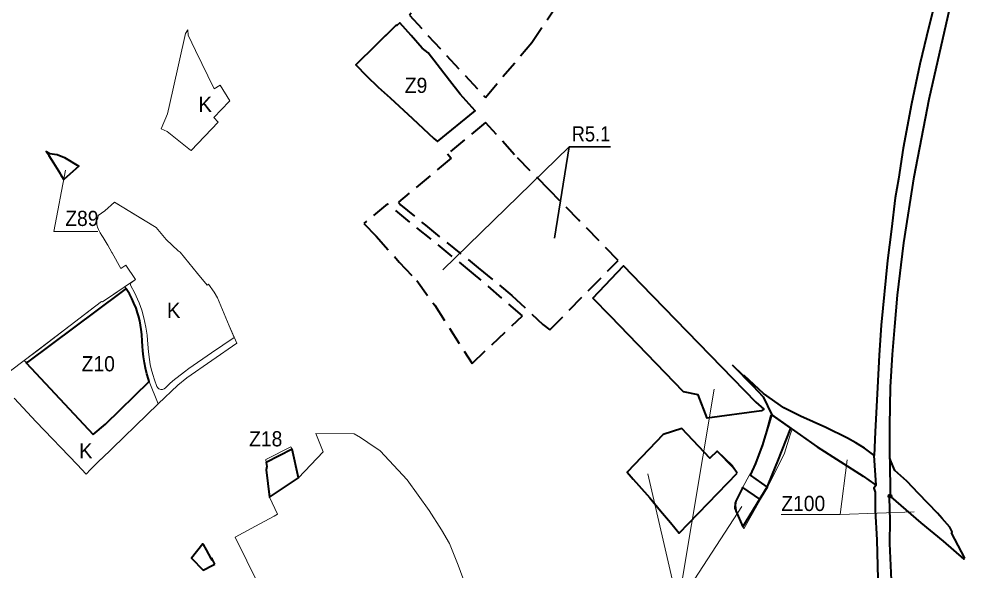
# Model space of a CAD drawing. Extents: x -650276 to -642489, y -1074311 to -1066658.
# Drawn here: x -646724 to -645222, y -1072621 to -1071749 of the extents above; entities that cross this region are included whole.
import ezdxf

# ---------------------------------------------------------------- set-up
doc = ezdxf.new("R2010")
doc.units = 0
doc.header["$LTSCALE"] = 9.6
doc.header["$PDMODE"] = 32
doc.header["$PDSIZE"] = 4.8
doc.linetypes.add('MEDIUM_DASHED', pattern=[4.5, 3, -1.5])
for name, color, linetype, lineweight in [('44', 7, 'Continuous', 40), ('45', 7, 'Continuous', 40), ('46', 7, 'Continuous', 13), ('47', 7, 'Continuous', 13), ('48', 7, 'Continuous', 13), ('61', 7, 'MEDIUM_DASHED', 40), ('62', 7, 'Continuous', 35), ('63', 7, 'Continuous', 13)]:
    doc.layers.add(name, color=color, linetype=linetype, lineweight=lineweight)

msp = doc.modelspace()

# ---------------------------------------------------------------- linework, layer by layer
at = {"layer": '44'}
for points in [[(-645347.551, -1072443.527), (-645347.677, -1072391.355), (-645346.62, -1072330.914), (-645343.458, -1072278.998), (-645339.908, -1072235.158), (-645335.367, -1072185.207), (-645325.498, -1072102.789), (-645309.01, -1071998.147), (-645285.617, -1071875.733), (-645244.798, -1071696.585), (-645235.793, -1071663.703), (-645230.436, -1071634.261), (-645227.905, -1071625.277), (-645222.48, -1071606.08)], [(-645261.094, -1071645.025), (-645264.841, -1071657.687), (-645269.077, -1071687.396), (-645274.868, -1071717.176), (-645286.175, -1071761.228), (-645300.076, -1071820.179), (-645313.153, -1071883.081)], [(-645313.153, -1071883.081), (-645326.343, -1071952.807), (-645334.118, -1072001.954), (-645339.455, -1072031.565), (-645344.819, -1072081.225), (-645351.358, -1072130.815), (-645361.317, -1072232.824), (-645364.435, -1072280.268), (-645366.951, -1072331.609), (-645370.624, -1072401.447), (-645372.228, -1072438.764)], [(-645369.364, -1072485.931), (-645372.228, -1072438.764), (-645373.099, -1072438.135), (-645387.894, -1072427.453), (-645401.441, -1072419.033), (-645414.631, -1072411.611), (-645448.831, -1072394.325), (-645488.64, -1072376.782), (-645515.437, -1072363.447), (-645547.593, -1072340.827), (-645577.33, -1072312.704), (-645579.217, -1072312.425), (-645596.405, -1072296.114)], [(-645596.405, -1072296.114), (-645564.4, -1072328.61), (-645547.72, -1072346.19), (-645534.301, -1072374.332), (-645462.646, -1072425.015)], [(-645462.646, -1072425.015), (-645389.731, -1072471.612), (-645372.013, -1072484.069), (-645369.364, -1072485.931)], [(-645339.904, -1072462.677), (-645342.953, -1072455.042), (-645347.551, -1072443.527), (-645347.292, -1072502.877)], [(-645228.96, -1072600.865), (-645249.9, -1072561.25), (-645248.967, -1072559.511), (-645252.768, -1072552.178), (-645265.009, -1072538.358), (-645272.276, -1072530.154), (-645302.303, -1072499.014), (-645320.805, -1072479.495), (-645339.904, -1072462.677)], [(-645369.364, -1072485.931), (-645372.72, -1072490.314), (-645370.928, -1072496.619), (-645370.755, -1072525.734), (-645368.173, -1072571.881), (-645366.022, -1072654.462), (-645364.524, -1072682.575), (-645364.786, -1072692.977), (-645362.708, -1072714.781)], [(-645338.023, -1072755.969), (-645339.96, -1072721.587), (-645344.152, -1072658.857), (-645347.795, -1072577.893), (-645347.214, -1072540.97), (-645348.253, -1072505.583), (-645347.292, -1072502.877)], [(-645347.292, -1072502.877), (-645346.093, -1072503.921), (-645298.498, -1072545.352)], [(-645298.498, -1072545.352), (-645263.217, -1072574.314), (-645230.845, -1072602.888), (-645228.96, -1072600.865)]]:
    msp.add_lwpolyline(points, dxfattribs=at)
msp.add_lwpolyline([(-646652.18, -1071967.73), (-646629.655, -1071981.343), (-646653.198, -1072002.544), (-646657.32, -1071995.98), (-646658.79, -1071993.62), (-646669.31, -1071976.77), (-646676.79, -1071964.97), (-646681.07, -1071958.16), (-646675.99, -1071961.64), (-646663.87, -1071963.26)], close=True, dxfattribs=at)
at = {"layer": '44', "lineweight": 13}
for points in [[(-646599.686, -1072084.891), (-646669.193, -1072084.891), (-646650.508, -1071987.658)], [(-646599.686, -1072084.891), (-646669.193, -1072084.891), (-646650.508, -1071987.658)], [(-645519.31, -1072532.095), (-645425.882, -1072532.095), (-645415.202, -1072445.813), (-645425.882, -1072532.095), (-645309.26, -1072527.964)], [(-645519.31, -1072532.095), (-645425.882, -1072532.095), (-645415.202, -1072445.813), (-645425.882, -1072532.095), (-645309.26, -1072527.964)]]:
    msp.add_lwpolyline(points, dxfattribs=at)
at = {"layer": '44'}
msp.add_point((-645347.292, -1072502.877), dxfattribs=at)
at = {"layer": '45'}
msp.add_line((-646417.787, -1072612.168), (-646414.77, -1072610.61), dxfattribs=at)
for points in [[(-646102.04, -1071906.4), (-646068.317, -1071937.555), (-646062.91, -1071942.55), (-646002.93, -1071893.984), (-646026.64, -1071867.44), (-646043.49, -1071845.87), (-646077.32, -1071802.59), (-646087, -1071795), (-646104.5, -1071774.86), (-646122.16, -1071754.78), (-646127.12, -1071759.15), (-646127.84, -1071758.53), (-646191.57, -1071821.44), (-646174.69, -1071838.69), (-646156.59, -1071856.53), (-646137.74, -1071873.31)], [(-645817.219, -1072189.975), (-645768.649, -1072139.283), (-645740.45, -1072168.23), (-645559.34, -1072354.42), (-645546.82, -1072365.72), (-645550.41, -1072368.47), (-645636.37, -1072379.57), (-645650.78, -1072342.73), (-645674, -1072338), (-645789.298, -1072218.833)], [(-646606.848, -1072405.785), (-646587.666, -1072389.082), (-646518.208, -1072321.92), (-646519.417, -1072318.408), (-646522.007, -1072309.932), (-646524.282, -1072300.849), (-646526, -1072292.201), (-646527.5, -1072282.657), (-646528.566, -1072273.308), (-646529.182, -1072265.941), (-646529.607, -1072258.124), (-646530.188, -1072247.442), (-646530.892, -1072239.747), (-646531.93, -1072232.861), (-646533.286, -1072226.031), (-646535.344, -1072217.844), (-646536.772, -1072213.218), (-646539.168, -1072206.122), (-646539.168, -1072206.122), (-646542.484, -1072197.985), (-646546.09, -1072190.428), (-646549.793, -1072183.38), (-646554.56, -1072175.629), (-646555.051, -1072174.933), (-646563.299, -1072181.091), (-646710.684, -1072291.133), (-646712.634, -1072292.59)], [(-645503.98, -1072395.64), (-645532.75, -1072375.41), (-645535.05, -1072376.72), (-645549.6, -1072423.39), (-645551.54, -1072428.66), (-645559.92, -1072451.41), (-645568.38, -1072469.68), (-645541.56, -1072488.74), (-645553.35, -1072508.1), (-645579.92, -1072489.22), (-645581.13, -1072491), (-645591.06, -1072511.06), (-645592.08, -1072517.43), (-645591.03, -1072526.14), (-645579.76, -1072551.45), (-645541.09, -1072487.98), (-645533.15, -1072468.21), (-645524.87, -1072447.61)], [(-645588.78, -1072467), (-645594.83, -1072458.48), (-645596.43, -1072455.42), (-645620.56, -1072432), (-645632.1, -1072442.93), (-645676.53, -1072396.16), (-645706.039, -1072405.769), (-645763.06, -1072465.26), (-645753.128, -1072476.383), (-645744.38, -1072486.18), (-645726.95, -1072505.7), (-645709.92, -1072526.3), (-645694.51, -1072544.93), (-645680.87, -1072561.42)], [(-645588.78, -1072467), (-645594.83, -1072458.48), (-645620.56, -1072432), (-645632.1, -1072442.93), (-645676.53, -1072396.16), (-645706.039, -1072405.769), (-645763.06, -1072465.26), (-645753.128, -1072476.383), (-645744.38, -1072486.18), (-645726.95, -1072505.7), (-645709.92, -1072526.3), (-645694.51, -1072544.93), (-645680.87, -1072561.42)], [(-646333.34, -1072461.67), (-646328.45, -1072504.81), (-646282.47, -1072474.34), (-646292.44, -1072428.89), (-646333.33, -1072450.12), (-646332.68, -1072456.19)], [(-646333.34, -1072461.67), (-646328.45, -1072504.81), (-646282.47, -1072474.34), (-646292.44, -1072428.89), (-646333.33, -1072450.12), (-646332.68, -1072456.19)]]:
    msp.add_lwpolyline(points, close=True, dxfattribs=at)
for points in [[(-646420.36, -1072601.78), (-646427.95, -1072588.07), (-646432.57, -1072579.75), (-646433.36, -1072578.45), (-646451.458, -1072601.008), (-646433.024, -1072620.04), (-646417.787, -1072612.168)], [(-646414.77, -1072610.61), (-646419.11, -1072602.03), (-646419.47, -1072601.31), (-646419.02, -1072604.18), (-646420.36, -1072601.78)]]:
    msp.add_lwpolyline(points, dxfattribs=at)
at = {"layer": '46'}
for q in [(-645625.498, -1072333.934), (-645729.938, -1072467.657), (-645729.938, -1072467.657), (-645581.338, -1072519.311)]:
    msp.add_line((-645682.434, -1072673.943), q, dxfattribs=at)
at = {"layer": '47'}
msp.add_line((-646490.111, -1071926.754), (-646453.04, -1071956.3), dxfattribs=at)
for points in [[(-646453.04, -1071956.3), (-646451.87, -1071956.88), (-646409.4, -1071912.17), (-646416.2, -1071904.81), (-646391.83, -1071879.32), (-646390.732, -1071878.171), (-646405.99, -1071853.26), (-646415.46, -1071859.05), (-646445.115, -1071798.418), (-646456.96, -1071774.2), (-646457.52, -1071765.98), (-646461.09, -1071771.76), (-646480.81, -1071861.18), (-646489.34, -1071898.61), (-646499.741, -1071922.455), (-646490.111, -1071926.754)], [(-646507.28, -1072078.4), (-646530.073, -1072064.559), (-646573.05, -1072038.46), (-646588.75, -1072052.06), (-646598.827, -1072059.244), (-646599.86, -1072063.71), (-646601, -1072067.55), (-646601.42, -1072071.01), (-646601.16, -1072074.07), (-646600.8, -1072075.94), (-646600.22, -1072077.86), (-646598.67, -1072081.55), (-646595.86, -1072086.82), (-646593.13, -1072091.01), (-646591.02, -1072094.4), (-646585.08, -1072104.81), (-646583.9, -1072106.42), (-646577.41, -1072117.76), (-646577.08, -1072118.7), (-646563.11, -1072143.03), (-646555.49, -1072138.17), (-646539.94, -1072160.83), (-646548.676, -1072166.737)], [(-646472.72, -1072115.38), (-646491.69, -1072097.45), (-646507.28, -1072078.4)], [(-646426.98, -1072169.74), (-646441.961, -1072151.281), (-646469.41, -1072117.44), (-646472.72, -1072115.38)], [(-646548.676, -1072166.737), (-646547.606, -1072170.835), (-646541.822, -1072181.102), (-646534.527, -1072197.411), (-646530.167, -1072209.31), (-646526.798, -1072221.011), (-646523.628, -1072235.883)], [(-646415.84, -1072180.43), (-646424.56, -1072167.96), (-646426.98, -1072169.74)], [(-646731.82, -1072348.2), (-646696.83, -1072385.81), (-646632.356, -1072453.247), (-646618.158, -1072468.098), (-646611.091, -1072460.994), (-646594.606, -1072444.422), (-646594.561, -1072444.38), (-646504.244, -1072357.026), (-646518.208, -1072321.92), (-646587.666, -1072389.082), (-646606.848, -1072405.785), (-646712.634, -1072292.59), (-646563.299, -1072181.091), (-646556.591, -1072176.083), (-646555.051, -1072174.933), (-646556.693, -1072172.16), (-646568.051, -1072179.84), (-646592.2, -1072196.17), (-646593.85, -1072195.48), (-646614.075, -1072210.952), (-646643.55, -1072233.5), (-646693.58, -1072271.606), (-646716.167, -1072288.809), (-646737.449, -1072305.019)], [(-646391.77, -1072233.91), (-646410.68, -1072189.36), (-646415.84, -1072180.43)], [(-646523.628, -1072235.883), (-646523.628, -1072235.883), (-646521.646, -1072248.378), (-646521.051, -1072256.707), (-646519.756, -1072274.861), (-646518.079, -1072287.051), (-646516.692, -1072294.983), (-646515.305, -1072301.925), (-646512.729, -1072311.048), (-646509.954, -1072319.377), (-646506.189, -1072329.889), (-646504.802, -1072331.971), (-646503.018, -1072333.459), (-646500.244, -1072334.45), (-646497.569, -1072334.55), (-646494.794, -1072333.558), (-646492.813, -1072332.07), (-646486.273, -1072325.526), (-646480.923, -1072320.667), (-646462.79, -1072306.784), (-646455.557, -1072301.131), (-646420.085, -1072276.737), (-646384.056, -1072252.138), (-646391.77, -1072233.91)], [(-645999.622, -1072714.927), (-646006.66, -1072681.4), (-646019.16, -1072642.35), (-646030.17, -1072612.31), (-646043.87, -1072578.12), (-646056.42, -1072556.49), (-646075.82, -1072525.54), (-646110.61, -1072477.49), (-646153.49, -1072431.54), (-646172.81, -1072418.2), (-646184.449, -1072410.256), (-646194.19, -1072404.62), (-646254.75, -1072404.25), (-646243.17, -1072432.88), (-646282.47, -1072474.34), (-646328.45, -1072504.81), (-646315.452, -1072531.573)], [(-646315.452, -1072531.573), (-646320.62, -1072534.6), (-646350.18, -1072550.59), (-646382.41, -1072568.01), (-646345.6, -1072642.55), (-646368.51, -1072652.81), (-646371.66, -1072654.2), (-646342.08, -1072717.43), (-646367.72, -1072730.68), (-646321.171, -1072780.535), (-646292.17, -1072811.6), (-646261.97, -1072849.66), (-646255.39, -1072850.83), (-646249.04, -1072847.16), (-646253.56, -1072838.8), (-646288.27, -1072810.22), (-646199.72, -1072763.1), (-646194.296, -1072760.193)]]:
    msp.add_lwpolyline(points, dxfattribs=at)
at = {"layer": '61'}
for points in [[(-645909.13, -1071478.56), (-645989, -1071611), (-646107, -1071743), (-645987.026, -1071872.902), (-645913.616, -1071786.041), (-645835.644, -1071670.191), (-645768.62, -1071540.17)], [(-645896.15, -1072231.57), (-645884.949, -1072239.96), (-645777.057, -1072130.664), (-645839.31, -1072066.947), (-645885.655, -1072019.486), (-645940.8, -1071963.54), (-645986.568, -1071912.301), (-646046.78, -1071962.265), (-646041.113, -1071969.094), (-646124.568, -1072038.344), (-646121.403, -1072042.471), (-646081.78, -1072075), (-645998.22, -1072142.19), (-645945, -1072186)], [(-646141.703, -1072041.072), (-646178.915, -1072071.95), (-646159.66, -1072092.31), (-646123.06, -1072133.18), (-646095.44, -1072162.47), (-646067.08, -1072201.18), (-646008.065, -1072293.22), (-645928.101, -1072218.151), (-646005.793, -1072151.499)]]:
    msp.add_lwpolyline(points, close=True, dxfattribs=at)
at = {"layer": '62'}
msp.add_line((-645854.421, -1071950.737), (-645877.767, -1072095.485), dxfattribs=at)
msp.add_lwpolyline([(-645789.051, -1071950.737), (-645854.421, -1071950.737), (-646054.422, -1072145.291)], dxfattribs=at)
at = {"layer": '63'}
msp.add_line((-646328.45, -1072504.81), (-646282.47, -1072474.34), dxfattribs=at)
for points in [[(-646122.16, -1071754.78), (-646127.12, -1071759.15), (-646127.84, -1071758.53), (-646136.12, -1071767.07), (-646191.57, -1071821.44), (-646174.69, -1071838.69), (-646156.59, -1071856.53), (-646137.74, -1071873.31)], [(-646068.317, -1071937.555), (-646062.91, -1071942.55), (-646002.93, -1071893.984), (-646026.64, -1071867.44), (-646077.32, -1071802.59), (-646087.3, -1071794.42), (-646122.16, -1071754.78)], [(-646137.74, -1071873.31), (-646137.74, -1071873.31), (-646102.04, -1071906.4), (-646068.317, -1071937.555)], [(-646573.05, -1072038.46), (-646588.75, -1072052.06), (-646598.827, -1072059.244), (-646599.86, -1072063.71), (-646601, -1072067.55), (-646601.42, -1072071.01), (-646601.16, -1072074.07), (-646600.8, -1072075.94), (-646600.22, -1072077.86), (-646598.67, -1072081.55), (-646595.86, -1072086.82)], [(-646380.12, -1072261.44), (-646391.77, -1072233.91), (-646410.68, -1072189.36), (-646415.84, -1072180.43), (-646424.56, -1072167.96), (-646426.98, -1072169.74), (-646441.961, -1072151.281), (-646469.41, -1072117.44), (-646472.72, -1072115.38), (-646491.69, -1072097.45), (-646507.28, -1072078.4), (-646573.05, -1072038.46)], [(-646595.86, -1072086.82), (-646593.13, -1072091.01), (-646591.02, -1072094.4), (-646585.08, -1072104.81), (-646583.9, -1072106.42), (-646577.41, -1072117.76), (-646577.08, -1072118.7)], [(-646577.08, -1072118.7), (-646563.11, -1072143.03), (-646555.49, -1072138.17), (-646539.94, -1072160.83), (-646592.2, -1072196.17), (-646593.85, -1072195.48), (-646643.55, -1072233.5), (-646716.167, -1072288.809)], [(-645546.82, -1072365.72), (-645559.34, -1072354.42), (-645602.003, -1072310.56), (-645705.999, -1072203.648), (-645740.45, -1072168.23), (-645768.649, -1072139.283), (-645817.219, -1072189.975), (-645674, -1072338)], [(-646504.244, -1072357.026), (-646473.069, -1072327.765), (-646459.03, -1072316.137), (-646380.12, -1072261.44)], [(-646716.167, -1072288.809), (-646693.755, -1072312.791), (-646693.755, -1072312.791)], [(-646693.755, -1072312.791), (-646606.848, -1072405.785), (-646587.666, -1072389.082), (-646518.208, -1072321.92), (-646504.244, -1072357.026)], [(-645674, -1072338), (-645650.78, -1072342.73), (-645636.37, -1072379.57), (-645550.41, -1072368.47), (-645546.82, -1072365.72)], [(-645578.609, -1072554.929), (-645537, -1072481), (-645514, -1072435), (-645505, -1072406), (-645502.215, -1072397.027), (-645534.301, -1072374.332)], [(-645534.301, -1072374.332), (-645536.14, -1072375.27), (-645546.39, -1072412.63), (-645558.04, -1072444.58)], [(-646282.47, -1072474.34), (-646292.44, -1072428.89), (-646294.51, -1072424.9), (-646332.82, -1072444.79), (-646333.84, -1072445.32), (-646333.33, -1072450.12), (-646332.68, -1072456.19), (-646333.34, -1072461.67), (-646328.45, -1072504.81)], [(-645558.04, -1072444.58), (-645565.34, -1072461.85), (-645570.132, -1072470.524), (-645580.109, -1072488.832), (-645592.85, -1072513.31)], [(-645592.85, -1072513.31), (-645593.23, -1072522.43), (-645578.609, -1072554.929)]]:
    msp.add_lwpolyline(points, dxfattribs=at)

# ---------------------------------------------------------------- texts
at = {"layer": '44', "width": 0.95}
for s, p in [('Z89', (-646651.144, -1072076.059)), ('Z89', (-646651.144, -1072076.059)), ('Z100', (-645519.262, -1072526.583)), ('Z100', (-645519.262, -1072526.583))]:
    msp.add_text(s, height=24, dxfattribs=at).set_placement(p)
at = {"layer": '46', "width": 0.95}
for s, p in [('Z9', (-646114.385, -1071865.725)), ('Z10', (-646625.207, -1072305.81)), ('Z18', (-646360.479, -1072424.402))]:
    msp.add_text(s, height=24, dxfattribs=at).set_placement(p)
at = {"layer": '48'}
for p in [(-646440.579, -1071895.779), (-646490.42, -1072221.403), (-646629.338, -1072443.411)]:
    msp.add_text('K', height=24, dxfattribs=at).set_placement(p)
at = {"layer": '62', "width": 0.9}
msp.add_text('R5.1', height=24, dxfattribs=at).set_placement((-645850.499, -1071942.459))

doc.saveas('drawing.dxf')
